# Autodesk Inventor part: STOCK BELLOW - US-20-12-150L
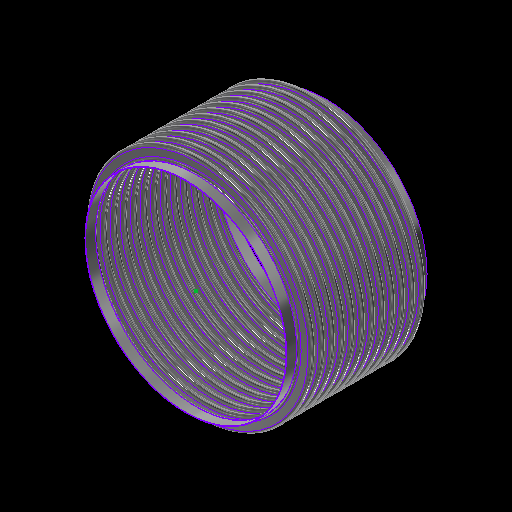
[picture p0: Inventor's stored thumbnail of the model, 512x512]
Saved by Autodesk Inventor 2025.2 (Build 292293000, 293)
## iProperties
Category: 16 GA (0.060 THICK)
RuleStatus: InUse
Created: 2024-01
Part Number: STOCK BELLOW - US-20-12-150L
Project: =STOCK BELLOWS: <Stock Number><SFILL>
Material: ASTM A240-304
Description: =STOCK BELLOWS: <Stock Number>, <SID_> I.D., <SOD_> O.D., <SPLY_> PLY, <Category>, <SNET_CONS> CONS.<PITCH_><STANGENT_> TANGENT<SFILL>
Document SubType Name: Sheet Metal
Designer: GS
Stock Number: U.S-20-12-150L
Surface Area: 32274.6 cm^2
Volume: 2448.17 cm^3
Sheet Metal Rule: Default
Appearance: STAINLESS STEEL
Mass: 19725.6 g
Density: 8.05729 g/cm^3
THK: 0.036
ID: 3.500
OD: 4.250
CONS_: 2
PITCH: 0.500
TANGENT: 0.500
BELLOWS_UPSET: 0.000
d79: 1.000
d82: 1.000
d83: 26.000
d84: 24.000
d174: 8
d214: 8
STHK_: 0.060
SID_: 20.000
SOD_: 22.500
SPITCH_: 1.000
STANGENT__: 1.000
SBELLOWS_UPSET_: 0.000
SDIFF_TAN: 1.000
d252: 2
d275: 2
d287: 0.050
d289: 0.500
d290: 0.000
SOD_NECK: 20 1/8
PLY: 1
PSET: 4.178
PBAR: 1.035
COUNTER: 1.500
NET_TUBE: 3.071
CONS: 2
S_CONS: 0
NET_CONS: 2
ID_M: 88.90 mm
OD_M: 107.95 mm
THK_M: 0.91 mm
ID_U: 3.500 in
OD_U: 4.250 in
THK_U: 0.036 in
TANGENT2: 0.500
TAN_TO_TAN: 1.000 in
d80: 2.571
d81: 10
SID: 2.375
SCONS_: 12
SPITCH: 0.250
STANGENT_: 1.000
SBELLOWS_UPSET: 0.000
SNET_CONS: 12
SS_CONS: 0
SCONS: 8
d190: 8
d191: 1
d192: 1
d193: 8
d194: 0
SIZE: 20.00
PRESSURE: 150
d230: 8
STANGENT: 4.000
SPLY_: 1
d233: 8
d234: 0
d263: 2
d265: 1
d268: 2
d269: 0
d286: 2
d288: 1
d291: 2
d292: 0
SREROLL: 0.750
BLETP: 1.000 ul
PRES_Copy: 85
MATTABLE: 20 GA (0.036 THICK)
PART_NUMBER: U.S-20-12-150L
PITCH_: =, <SPITCH_> PITCH,
CFILL: .
SFILL: .
MESH: ,
COMP: 2.24
EXT: 1.12
LAT: 0.42
ANG: 573
ASR: 3755
LSR: 15895
ANSR: 3329
PRES: 150
COMPM: 22.4
EXTM: 11.2
LATM: 4.20
ASRM: 657.613
PRESM: 10.342
LSRM: 2783.691
ANSRM: 583.008
TEMPMIN: 20
TEMPMAX: 800
TEMPMINM: -7
TEMPMAXM: 427
WEIGHTM: 19.726
WEIGHT: 43.488
Author: GS
Keywords: 20 GA (0.036 THICK)
Comments: =STOCK BELLOW - <STOCK NUMBER>
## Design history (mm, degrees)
sketch "Sketch2"
  geometry: L1 (0, -177.245)-(0, 562.856) reference; L2 (45.364, 0)-(44.45, 0); L3 (48.082, -2.718)-(50.343, -2.718); L4 (48.082, -3.632)-(50.343, -3.632); L5 (50.343, -9.982)-(48.082, -9.982); L6 (50.343, -9.068)-(48.082, -9.068); L7 (45.364, -12.7)-(44.45, -12.7); L8 (48.082, 0)-(48.082, -12.7); L9 (50.343, -6.35)-(53.975, -6.35); L10 (44.45, 0)-(44.45, -12.7); L11 (20.376, 102.841)-(20.376, 101.926); L12 (58.262, 457.127)-(58.262, 349.177); L13 (58.262, 444.427)-(58.262, 336.477); L14 (93.133, -58.817)-(93.133, -71.517); L15 (118.746, -66.401)-(118.746, -66.401); L16 (50.343, -9.068)-(50.343, -9.982); L17 (48.082, -9.068)-(48.082, -9.982); L18 (48.082, -9.525)-(50.343, -9.525); L19 (53.975, 0)-(53.975, -12.7); L20 (-50.343, -9.068)-(-50.343, -9.982); L21 (-50.343, -2.718)-(-48.082, -2.718); L22 (-50.343, -3.632)-(-48.082, -3.632); L23 (-48.082, -9.068)-(-50.343, -9.068); L24 (-50.343, -9.525)-(-48.082, -9.525); L25 (-48.082, -9.982)-(-50.343, -9.982); L26 (-48.082, -9.068)-(-48.082, -9.982); L27 (-44.45, 0.653)-(-44.45, -12.047); L28 (-48.082, -6.35)-(-44.45, -6.35); L29 (-50.343, 0.653)-(-50.343, -12.7); L30 (-53.061, 0)-(-53.975, 0); L31 (-53.975, 0)-(-53.975, -12.7); L32 (-53.061, -12.7)-(-53.975, -12.7); A1 r 2.718 centre (48.082, 0) between (45.364, 0) and (48.082, -2.718); A2 r 3.632 centre (48.082, 0) between (44.45, 0) and (48.082, -3.632); A3 r 3.632 centre (50.343, -6.35) between (50.343, -9.982) and (50.343, -2.718); A4 r 2.718 centre (50.343, -6.35) between (50.343, -9.068) and (50.343, -3.632); A5 r 2.718 centre (48.082, -12.7) between (48.082, -9.982) and (45.364, -12.7); A6 r 3.632 centre (48.082, -12.7) between (48.082, -9.068) and (44.45, -12.7); A7 r 3.175 centre (50.343, -6.35) between (50.343, -9.525) and (53.518, -6.35); A8 r 3.175 centre (48.082, -12.7) between (48.082, -9.525) and (44.907, -12.7); A9 r 2.718 centre (-50.343, -12.7) between (-50.343, -9.982) and (-53.061, -12.7); A10 r 2.718 centre (-48.082, -6.35) between (-48.082, -9.068) and (-48.082, -3.632); A11 r 3.175 centre (-48.082, -6.35) between (-48.082, -9.525) and (-44.907, -6.35); A12 r 3.632 centre (-48.082, -6.35) between (-48.082, -9.982) and (-48.082, -2.718); A13 r 3.175 centre (-50.343, -12.7) between (-50.343, -9.525) and (-53.518, -12.7); A14 r 3.632 centre (-50.343, -12.7) between (-50.343, -9.068) and (-53.975, -12.7); A15 r 2.718 centre (-50.343, 0) between (-53.061, 0) and (-50.343, -2.718); A16 r 3.632 centre (-50.343, 0) between (-53.975, 0) and (-50.343, -3.632); 10 further points
  constraints: 62 end point, 38 point on circle, 20 tangent, 16 centre point, 12 parallel, 9 midpoint, 7 vertical, 6 coincident, 6 concentric, 6 point on line, 4 equal radius, 4 perpendicular, 3 horizontal, 1 collinear, 1 horizontal alignment, 10 other
  dimensions: "THK" = 0.9144 distance of L11.start L11.end; "ID" = 88.9 distance of L11.end point (20.376, 13.026); "OD" = 107.95 distance of L12.start L12.end; "PITCH" = 12.7 distance of L12.start L13.start; "TANGENT" = 12.7 distance of L14.start L14.end; "BELLOWS_UPSET" = 0 distance of L15.start L15.end; "d43" = 88.9 diameter of L10 L1 (= ID); "d44" = 107.95 diameter of L9.end L1 (= OD); "d45" = 0.9144 distance between parallel lines of L5 L6 (computed from THK, PLY); "d46" = 3.6322 radius of A3 (computed from PITCH, THK, PLY); "UPSET_PITCH" = 12.7 distance of L2.end L7.end (derived); "SIDEWALL_ANGLE" = 360 deg dimension on L3 L9 (derived); "CON_GAP" = 5.4356 distance of point (48.082, -9.068) point (48.082, -3.632) (derived); "TAN1" = 4.98728 dimension on A8 (derived); "TAN2" = 4.98728 dimension on A7 (derived); "LEG1" = 2.2606 distance of L18.start L18.end (derived); "d278" = 0.9144 distance between parallel lines of L25 L23 (derived); "d279" = 3.6322 radius of A12 (derived); "d280" = 12.7 distance of L30.end L31.end (derived); "d281" = 360 deg dimension on L21 L28 (derived); "d282" = 5.4356 distance of point (-50.343, -9.068) point (-50.343, -3.632) (derived); "d283" = 4.98728 dimension on A13 (derived); "d284" = 4.98728 dimension on A11 (derived); "d285" = 2.2606 distance of L24.start L24.end (derived); "d293" = 88.9 diameter of L27 L1 (derived); "d294" = 107.95 diameter of L31 L1 (derived)
  node "Sketch Rectangular Pattern1" dims "d31" = 25.4, "ID" = 88.9
  node "Sketch Rectangular Pattern2" dims "d39" = 25.4, "PITCH" = 12.7
revolve "CONS" stored, may be unused: angle "d48" = 90 deg
node "BELLOW MIDPLANE"
pattern_linear "Rectangular Pattern2" dims "d52" = 12.7 (= UPSET_PITCH)
sketch "Sketch5"
  geometry: C1 r 45.364 at (0, 0) reference; C2 r 44.45 at (0, 0) reference
extrude "TANGENT" new body sketch "Sketch5" distance "d53" = 12.7 (= TANGENT); taper "d54" = 0 deg
revolve "SAMETAN" stored, may be unused: angle "d65" = 90 deg
revolve "DIFFTAN" stored, may be unused: angle "d70" = 90 deg
sketch "Sketch9"
  geometry: L1 (53.319, 0)-(-53.319, 0) reference; L2 (0, -17.78)-(0, 17.78) reference; L3 (38.085, 0)-(-38.085, 0); L4 (38.085, -11.906)-(38.085, 11.906); L5 (25.385, -11.906)-(25.385, 11.906); L6 (13.15, 11.906)-(13.15, -11.906); L7 (-25.385, -11.906)-(-25.385, 11.906); L8 (-38.085, -11.906)-(-38.085, 11.906); L9 (37.291, -11.906)-(37.291, 11.906); L10 (38.085, -11.906)-(37.291, -11.906); L11 (38.085, 11.906)-(37.291, 11.906); L12 (13.546, 11.906)-(12.753, 11.906); L13 (12.753, 11.906)-(12.753, -11.906); L14 (12.753, -11.906)-(13.546, -11.906); L15 (13.546, -11.906)-(13.546, 11.906); L16 (-13.546, 11.906)-(-13.546, -11.906); L17 (-13.15, 11.906)-(-13.15, -11.906); L18 (-13.546, -11.906)-(-12.753, -11.906); L19 (-12.753, -11.906)-(-12.753, 11.906); L20 (-12.753, 11.906)-(-13.546, 11.906); L21 (-38.085, -11.906)-(-37.291, -11.906); L22 (-37.291, -11.906)-(-37.291, 11.906); L23 (-37.291, 11.906)-(-38.085, 11.906); L24 (-38.085, 11.906)-(-38.085, -11.906); L25 (38.085, -0.397)-(-38.085, -0.397); L26 (-38.085, -0.397)-(-38.085, 0.397); L27 (-38.085, 0.397)-(38.085, 0.397); L28 (38.085, 0.397)-(38.085, -0.397); L29 (-38.085, 11.906)-(38.085, 11.906); L30 (38.085, 11.906)-(38.085, 12.7); L31 (38.085, 12.7)-(-38.085, 12.7); L32 (-38.085, 12.7)-(-38.085, 11.906); L33 (38.085, -11.906)-(-38.085, -11.906); L34 (-38.085, -11.906)-(-38.085, -12.7); L35 (-38.085, -12.7)-(38.085, -12.7); L36 (38.085, -12.7)-(38.085, -11.906); 30 further points
  constraints: 68 end point, 13 midpoint, 13 parallel, 8 horizontal, 7 perpendicular, 6 equal length, 3 point on line, 2 vertical, 14 other
  dimensions: "d115" = 23.8125 distance of L4.start L4.end (derived); "d116" = 12.7 distance between parallel lines of L4 L5 (derived); "d117" = 12.23516 distance between parallel lines of L5 L6 (derived); "d125" = 38.53427 distance between parallel lines of L7 L6 (derived); "d127" = 12.7 distance between parallel lines of L8 L7 (derived); "d128" = 24.93516 distance between parallel lines of L6 L4 (derived); "d130" = 76.16943 distance between parallel lines of L8 L4 (derived); "RULER_THK" = 0.79375 distance between parallel lines of L4 L9; "d135" = 0.79375 distance of L13.end L14.end (derived); "d138" = 26.29911 distance of L13.end L16.end (derived); "d143" = 0.79375 distance of L22.end L8.end (derived); "d144" = 0.79375 distance between parallel lines of L27 L25 (derived)
extrude "RULER" join sketch "Sketch9" distance "d149" = 0.79375 (derived); taper "d150" = 0 deg
extrude "BARS" join sketch "Sketch9" distance "d151" = 0.79375 (derived); taper "d152" = 0 deg
pattern_linear "Rectangular Pattern4" dims "d155" = 26.29911 (derived)
sketch "Sketch13"
  geometry: L1 (93.149, -52.467)-(93.149, -77.867); L2 (255.524, 0)-(254, 0); L3 (255.524, -25.4)-(254, -25.4); L4 (278.638, -19.812)-(261.112, -19.812); L5 (278.638, -18.288)-(261.112, -18.288); L6 (278.638, -12.7)-(285.75, -12.7); L7 (261.112, -5.588)-(278.638, -5.588); L8 (261.112, 0)-(261.112, -25.4); L9 (254, 0)-(254, -25.4); L10 (58.254, 75.069)-(58.254, -496.431); L11 (58.254, 49.669)-(58.254, -521.831); L12 (58.254, -1.131)-(58.254, -572.631); L13 (58.254, -26.531)-(58.254, -598.031); L14 (58.254, -51.931)-(58.254, -623.431); L15 (58.254, -77.331)-(58.254, -648.831); L16 (58.254, -102.731)-(58.254, -674.231); L17 (58.254, 24.269)-(58.254, -547.231); L18 (20.376, 103.45)-(20.376, 101.926); L19 (261.112, -7.112)-(278.638, -7.112); L20 (0, -829.767)-(0, 258.986) reference; L21 (-57.15, 0)-(342.9, 0) reference; A1 r 5.588 centre (261.112, 0) between (255.524, 0) and (261.112, -5.588); A2 r 5.588 centre (261.112, -25.4) between (261.112, -19.812) and (255.524, -25.4); A3 r 7.112 centre (261.112, -25.4) between (261.112, -18.288) and (254, -25.4); A4 r 5.588 centre (278.638, -12.7) between (278.638, -18.288) and (278.638, -7.112); A5 r 7.112 centre (278.638, -12.7) between (278.638, -19.812) and (278.638, -5.588); A6 r 7.112 centre (261.112, 0) between (254, 0) and (261.112, -7.112); 6 further points; 1 other entity
  constraints: 38 end point, 15 point on circle, 9 tangent, 6 centre point, 6 parallel, 5 vertical alignment, 4 point on line, 4 vertical, 3 coincident, 3 concentric, 2 collinear, 2 equal radius, 1 horizontal, 1 perpendicular, 23 other
  dimensions: "SBELLOWS_UPSET_" = 0 distance of point (118.762, -66.401) point (118.762, -66.401); "STOTAL_THK_BELLOW__" = 1.524 distance between parallel lines of L4 L5 (derived); "d224" = 7.112 radius of A5 (derived); "d225" = 25.4 distance of L2.end L3.end (derived); "SSIDEWALL_ANGLE_" = 360 deg dimension on L7 L6 (derived); "SSCON_GAP_" = 11.176 distance of point (261.112, -18.288) point (261.112, -7.112) (derived); "d235" = 508 diameter of L9 L20 (derived); "d236" = 571.5 diameter of L6.end L20 (derived)
  node "Sketch Rectangular Pattern4" dims "d228" = 25.4
  node "Sketch Rectangular Pattern5" dims "d229" = 25.4
revolve "SBELLOW" stored, may be unused: angle "d197" = 90 deg
pattern_linear "Rectangular Pattern5" dims "d204" = 25.4 (derived)
revolve "STANGENT" stored, may be unused: angle "d240" = 90 deg
revolve "SSAMETAN" stored, may be unused: angle "d241" = 90 deg
revolve "SDIFFTAN" stored, may be unused: angle "d246" = 90 deg
revolve "INVCON" stored, may be unused: angle "d295" = 90 deg
pattern_linear "Rectangular Pattern6" dims "d298" = 12.7 (derived)
revolve "INVTANGENT" stored, may be unused: angle "d302" = 90 deg
revolve "INVSAMETAN" stored, may be unused: angle "d307" = 90 deg
revolve "INVDIFFTAN" stored, may be unused: angle "d312" = 90 deg
sketch "ID BELLOW MOUNT CALC"
  geometry: L1 (44.45, 0)-(38.1, 0); L2 (38.1, 0)-(38.1, 12.7); L3 (38.1, 12.7)-(44.45, 12.7); L4 (44.45, 12.7)-(44.45, 0); L5 (36.513, 12.7)-(35.598, 12.7); L6 (35.598, 12.7)-(35.598, 0); L7 (35.598, 0)-(36.513, 0); L8 (36.513, 0)-(36.513, 12.7); L9 (0, -2.54)-(0, 15.24) reference; L10 (-8.89, 0)-(53.34, 0) reference; 1 further point
  constraints: 16 end point, 5 parallel, 2 collinear, 2 horizontal, 2 perpendicular
  dimensions: "d314" = 12.7 distance of L5.end L6.end (derived); "d315" = 0.9144 distance of L5.start L5.end (derived); "IG" = 1.5875 distance between parallel lines of L2 L8; "PIPE_OD" = 88.9 diameter of L4 L9; "PIPE_WALL" = 6.35 distance of L2.end L3.end; "ID_MT_BELLOW" = 71.1962 diameter of L6 L9 (derived)
revolve "CFILL" stored, may be unused: angle "d320" = 90 deg
pattern_linear "Rectangular Pattern7" dims "d323" = 12.7 (derived)
revolve "SFILL" stored, may be unused: angle "d324" = 90 deg
pattern_linear "Rectangular Pattern8" dims "d327" = 25.4 (derived)
node "STOCK BELLOW MIDPLANE"
node "BELLOW"
sketch "Sketch6"
  geometry: L1 (-12.7, 45.364)-(0, 45.364); L2 (0, 45.364)-(0, 44.45); L3 (0, 44.45)-(-12.7, 44.45); L4 (-12.7, 44.45)-(-12.7, 45.364); L5 (10.16, 0)-(-60.96, 0) reference; L6 (-38.1, -89.422)-(-38.1, 153.44) reference; 1 further point
  constraints: 8 end point, 2 parallel, 1 horizontal, 1 perpendicular
  dimensions: "d61" = 12.7 distance of L2.end L3.end (derived); "d62" = 0.9144 distance of L1.end L2.end (derived); "d63" = 88.9 diameter of L3 L5 (derived); "d64" = 25.4 distance between parallel lines of L4 L6 (derived)
sketch "Sketch12"
  geometry: 1 further point
sketch "Sketch14"
  geometry: L1 (-25.4, 255.524)-(0, 255.524); L2 (0, 255.524)-(0, 254); L3 (0, 254)-(-25.4, 254); L4 (-25.4, 254)-(-25.4, 255.524); L5 (5.08, 0)-(-30.48, 0) reference; L6 (0, -51.105)-(0, 306.629) reference; 1 further point
  constraints: 8 end point, 2 parallel, 1 collinear, 1 horizontal, 1 perpendicular
  dimensions: "d237" = 1.524 distance of L3.end L1.start (derived); "d238" = 508 diameter of L3 L5 (derived); "d239" = 25.4 distance of L1.start L1.end (derived); "SOD_NECK" = 511.048 diameter of L1 L5 (derived)
sketch "Sketch15"
  geometry: L1 (-51.105, 0)-(306.629, 0) reference; L2 (254, -304.8)-(255.524, -304.8); L3 (255.524, -304.8)-(255.524, -330.2); L4 (255.524, -330.2)-(254, -330.2); L5 (254, -330.2)-(254, -304.8); L6 (0, -398.78)-(0, 81.28) reference; 1 further point
  constraints: 8 end point, 2 parallel, 1 horizontal, 1 perpendicular
  dimensions: "d205" = 25.4 distance of L4.end L2.start (derived); "d206" = 1.524 distance of L3.end L4.end (derived); "d207" = 508 diameter of L5 L6 (derived); "d208" = 304.8 distance between parallel lines of L1 L2 (derived)
node "TANGENT_"
node "SAME_TAN"
sketch "Sketch8"
  geometry: L1 (45.364, -25.4)-(44.45, -25.4); L2 (44.45, -25.4)-(44.45, -38.1); L3 (44.45, -38.1)-(45.364, -38.1); L4 (45.364, -38.1)-(45.364, -25.4); L5 (0, -48.26)-(0, 22.86) reference; L6 (-89.422, 0)-(153.44, 0) reference; 1 further point
  constraints: 8 end point, 2 parallel, 1 horizontal, 1 perpendicular
  dimensions: "d66" = 88.9 diameter of L2 L5 (derived); "TOTAL_THK_BELLOW" = 0.9144 distance of L2.end L3.end (derived); "d68" = 25.4 distance between parallel lines of L1 L6 (derived); "d69" = 12.7 distance of L1.end L2.end (derived)
node "DIFF_TAN"
node "Sketch Rectangular Pattern3" dims "d138" = 26.29911 (derived), "d141" = 25.4
node "SBELLOW_"
node "STANGENT_"
node "SSAME_TAN"
sketch "Sketch16"
  geometry: L1 (255.524, -304.8)-(254, -304.8); L2 (254, -304.8)-(254, -330.2); L3 (254, -330.2)-(255.524, -330.2); L4 (255.524, -330.2)-(255.524, -304.8); L5 (0, -398.78)-(0, 81.28) reference; L6 (-51.105, 0)-(306.629, 0) reference; 1 further point
  constraints: 8 end point, 2 parallel, 1 horizontal, 1 perpendicular
  dimensions: "SDIFF_TAN" = 25.4 distance of L3.end L1.start; "d243" = 1.524 distance of L2.end L3.end (derived); "d244" = 304.8 distance between parallel lines of L1 L6 (derived); "d245" = 508 diameter of L2 L5 (derived)
node "SDIFF_TAN"
body "Solid15"
sketch "Sketch17"
  geometry: L1 (53.975, 12.7)-(53.061, 12.7); L2 (53.061, 12.7)-(53.061, 0); L3 (53.061, 0)-(53.975, 0); L4 (53.975, 0)-(53.975, 12.7); L5 (0, -2.54)-(0, 15.24) reference; L6 (-10.795, 0)-(64.77, 0) reference; 2 further points
  constraints: 8 end point, 2 parallel, 1 horizontal, 1 midpoint, 1 perpendicular, 1 point on line
  dimensions: "INVTANGENT" = 12.7 distance of L3.end L1.start (derived); "d300" = 0.9144 distance of L1.start L1.end (derived); "d301" = 107.95 diameter of L4 L5 (derived)
body "Solid16"
sketch "Sketch18"
  geometry: L1 (53.975, -25.4)-(53.061, -25.4); L2 (53.061, -25.4)-(53.061, -38.1); L3 (53.061, -38.1)-(53.975, -38.1); L4 (53.975, -38.1)-(53.975, -25.4); L5 (-10.795, 0)-(64.77, 0) reference; L6 (0, -48.26)-(0, 22.86) reference; 1 further point
  constraints: 8 end point, 2 parallel, 1 horizontal, 1 perpendicular
  dimensions: "d303" = 25.4 distance between parallel lines of L1 L5 (derived); "d304" = 12.7 distance of L3.end L1.start (derived); "d305" = 0.9144 distance of L2.end L3.end (derived); "d306" = 107.95 diameter of L4 L6 (derived)
body "Solid17"
sketch "Sketch19"
  geometry: L1 (53.975, -25.4)-(53.061, -25.4); L2 (53.061, -25.4)-(53.061, -38.1); L3 (53.061, -38.1)-(53.975, -38.1); L4 (53.975, -38.1)-(53.975, -25.4); L5 (0, -48.26)-(0, 22.86) reference; L6 (-10.795, 0)-(64.77, 0) reference; 1 further point
  constraints: 8 end point, 2 parallel, 1 horizontal, 1 perpendicular
  dimensions: "d308" = 12.7 distance of L1.end L2.end (derived); "d309" = 107.95 diameter of L4 L5 (derived); "d310" = 0.9144 distance of L2.end L3.end (derived); "d311" = 25.4 distance between parallel lines of L1 L6 (derived)
body "Solid18"
body "Solid19"
body "Solid20"
other parameters: "BMPL" = -152.4, "PSET" = 106.1212 (computed from OD, THK, PLY) [user parameter], "PBAR" = 26.29911 (= 0.570796 x PITCH + OD - ID) [user parameter; used in 1 equation term], "COUNTER" = 15 [user parameter], "NET_TUBE" = 77.99823 (computed from CONS_, PBAR, TANGENT) [user parameter], "S_CONS" = 0 [user parameter; used in 1 equation term], "ID_M" = 88.9 (= ID) [user parameter], "OD_M" = 107.95 (= OD) [user parameter], "THK_M" = 0.9144 (= THK) [user parameter], "ID_U" = 88.9 (= ID) [user parameter], "OD_U" = 107.95 (= OD) [user parameter], "THK_U" = 0.9144 (= THK) [user parameter], "D_UNITS" = 0 [user parameter], "TANGENT2" = 12.7 [user parameter], "TAN_TO_TAN" = 25.4 [user parameter], "OD_NECK" = 90.7288 [user parameter], "d79" = 25.4, "d80" = 65.29823 [user parameter], "d82" = 25.4, "d83" = 660.4, "d84" = 609.6, "sa_0" = 4, "FRAME_THK" = 0.79375 [user parameter], "CON_FLAT" = 12.23516 [user parameter], "SID" = 60.325 [user parameter], "SPITCH" = 6.35 [user parameter], "STANGENT_" = 25.4 [user parameter], "SBELLOWS_UPSET" = 0 [user parameter], "SS_CONS" = 0 [user parameter], "STAN_TO_TAN_" = 304.8 [user parameter], "d100" = 1.524 [user parameter], "d191" = 25.4 [user parameter], "d194" = 0 [user parameter], "STANGENT" = 101.6 [user parameter], "d234" = 0 [user parameter], "SUPSET_PITCH_" = 25.4 [user parameter], "d269" = 0 [user parameter], "d287" = 1.27, "d289" = 12.7, "d290" = 0, "d292" = 0 [user parameter], "Thickness" = 3.048 (derived), "KFactor" = 4.4, "BendRadius" = 3.048 (derived), "BendReliefWidth" = 3.048 (derived), "BendReliefDepth" = 1.524 (derived), "CornerReliefSize" = 12.192 (derived), "SeamGap" = 0.00508, "MinimumRemnant" = 6.096 (derived), "TransitionRadius" = 3.048 (derived), "JacobiRadiusSize" = 3.048 (derived), "GapSize" = 3.048 (derived), "SREROLL" = 19.05 [user parameter], "CUR_STK_PITCH" = 25.4 [user parameter], "d328" = -152.4 (derived), "ASR" = 37550 [user parameter], "LSR" = 158950 [user parameter], "ANSR" = 33290 [user parameter], "BLETP" = 1 [user parameter], "ASRM" = 6576.1315 [user parameter], "PRESM" = 103.41975 [user parameter], "LSRM" = 27836.9135 [user parameter], "ANSRM" = 5830.0777 [user parameter], "TEMPMIN" = 2664.83333 [user parameter], "TEMPMAX" = 6998.16667 [user parameter], "TEMPMINM" = 2664.83333 [user parameter], "TEMPMAXM" = 6998.16667 [user parameter], "WEIGHT" = 197.25609 [user parameter], "WEIGHTM" = 0.19726 [user parameter]
